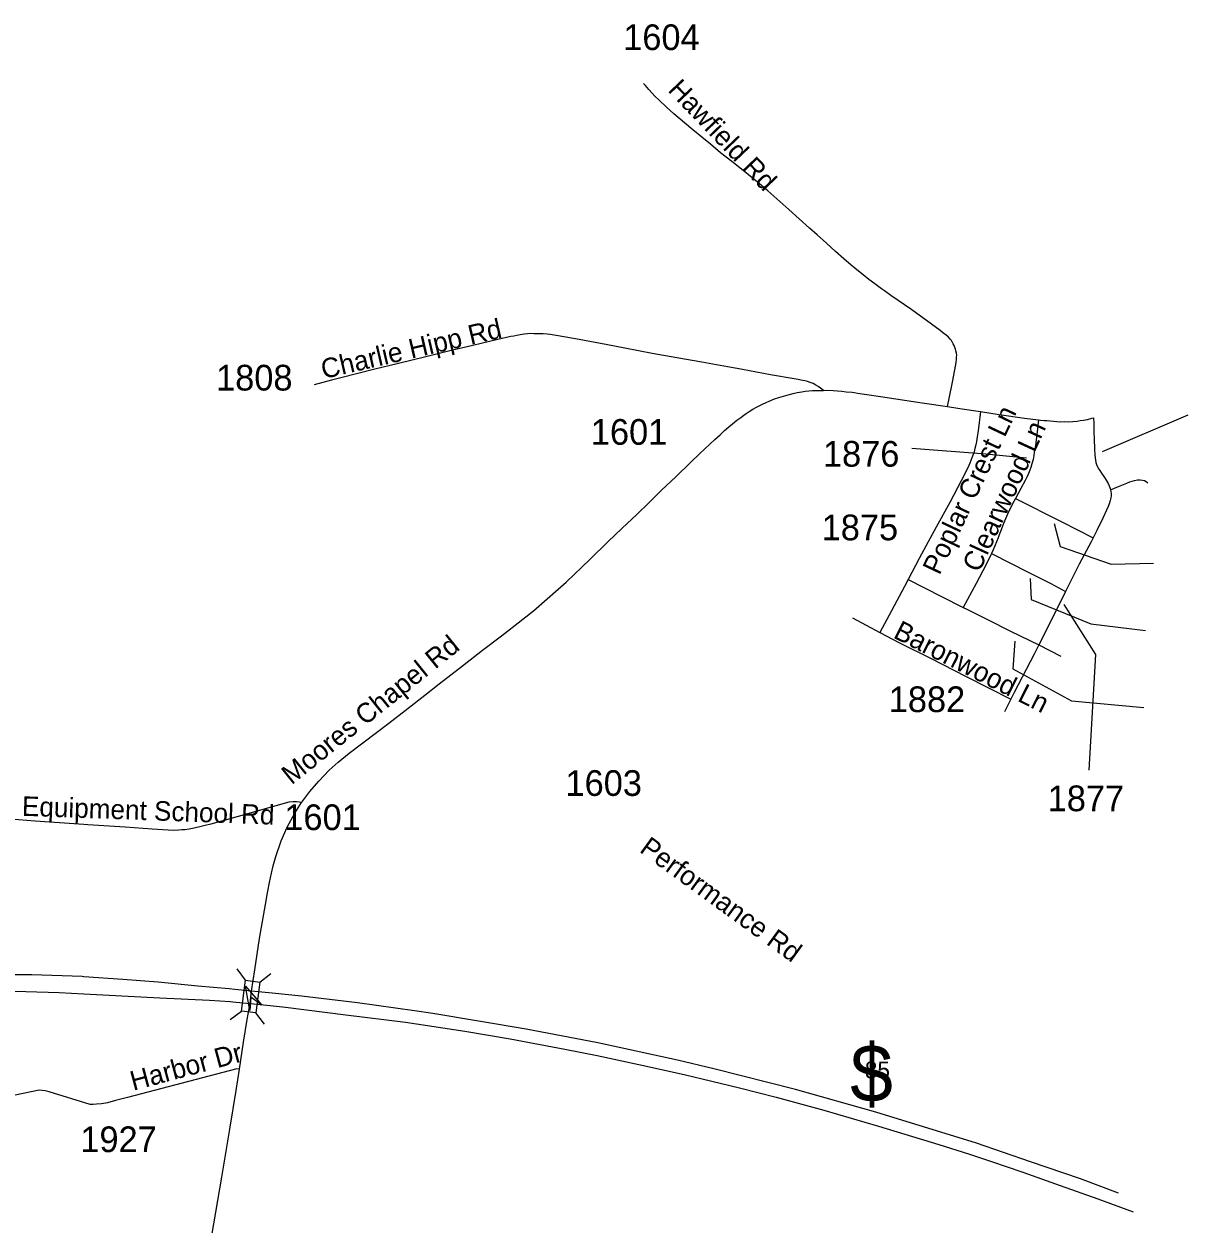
# Model space of a CAD drawing. Extents: x 1364363 to 1407445, y 538563 to 573342.
# Drawn here: x 1401783 to 1407445, y 553749 to 559586 of the extents above; entities that cross this region are included whole.
import ezdxf

# ---------------------------------------------------------------- set-up
doc = ezdxf.new("R2010")
doc.units = 0
for name, color, linetype in [('Default', 7, 'Continuous'), ('Exist Road Primary Interstate Divided Center Attributed', 7, 'Continuous'), ('Exist Road Primary Interstate Shield CELL', 7, 'Continuous'), ('Exist Road Secondary Structure Standard Bridge Attributed CELL', 7, 'Continuous'), ('Exist Road Secondary Structure Standard Bridge CELL', 7, 'Continuous'), ('Exist Road Secondary Type 51 Attributed', 7, 'Continuous'), ('Exist Road Secondary Type 51 Label', 7, 'Continuous'), ('Exist Road Secondary Type 51 Number Label', 7, 'Continuous')]:
    doc.layers.add(name, color=color, linetype=linetype)

msp = doc.modelspace()

# ---------------------------------------------------------------- linework, layer by layer
at = {"layer": 'Exist Road Primary Interstate Divided Center Attributed'}
for points in [[(1402889.9, 554881.6), (1402809.6, 554889.8), (1402781.4, 554892.7), (1402628.7, 554906.1), (1402436.1, 554924.4), (1402264.4, 554938.2), (1402075, 554951.4), (1402066.2, 554951.9), (1401820.9, 554959.8), (1401703.2, 554961.2), (1401454.2, 554964.3), (1401140.9, 554963), (1400812.9, 554956.8), (1400615.7, 554948.8), (1400380.2, 554939.8), (1400229.5, 554933.3), (1400151.5, 554930.7), (1400046.8, 554927.3), (1399813.2, 554921.2), (1399668.9, 554919.2), (1399415.1, 554904.8), (1399267.1, 554899.4), (1398949.5, 554886), (1398849.6, 554881.8)], [(1398871.8, 554808), (1399139.7, 554819.3), (1399383.9, 554824.3), (1399558.4, 554831.4), (1399816.6, 554844.8), (1399967.8, 554848.3), (1400081.5, 554856), (1400107.8, 554857.8), (1400231.2, 554866.9), (1400703.7, 554883.3), (1401109.6, 554891.3), (1401566.5, 554885.6), (1401573.3, 554885.6), (1401953.8, 554874.5), (1402075, 554867.8), (1402227.7, 554859.3), (1402444.7, 554849.5), (1402685, 554837.7), (1402785.5, 554830.5), (1402799.6, 554829.3), (1402883.2, 554821.9)], [(1407107.1, 553899.3), (1406922.5, 553967.7), (1406679.8, 554051.5), (1406415.7, 554141.3), (1405927.6, 554293.3), (1405535.4, 554403.2), (1405139.5, 554502.8), (1404962.1, 554544.8), (1404574.2, 554629.1), (1404225.4, 554696.7), (1403771.2, 554771.9), (1403682.1, 554785.3), (1403405, 554824), (1403132.7, 554856.6), (1402990.2, 554871.2), (1402889.9, 554881.6)], [(1402883.2, 554821.9), (1402981.1, 554811.5), (1403055.8, 554803.3), (1403349.3, 554766.2), (1403639.3, 554730.4), (1403927.4, 554686.4), (1404147.8, 554648.5), (1404413.6, 554599.2), (1404571.6, 554567.5), (1404774.7, 554524.1), (1404995.3, 554475), (1405263.1, 554411.3), (1405442.5, 554365.5), (1405674, 554302.7), (1405939.6, 554223.7), (1406233.8, 554135.9), (1406377.3, 554090.6), (1406489.5, 554052.4), (1406641.3, 554001.4), (1406824.2, 553936.6), (1407006.2, 553870.3), (1407178.2, 553807)]]:
    msp.add_lwpolyline(points, dxfattribs=at)
at = {"layer": 'Exist Road Secondary Structure Standard Bridge Attributed CELL'}
msp.add_lwpolyline([(1402882.6, 554786.3), (1402860.2, 554906.2), (1402939.5, 554813.5), (1402886.5, 554851.2)], close=True, dxfattribs=at)
at = {"layer": 'Exist Road Secondary Structure Standard Bridge CELL'}
for p, q in [((1402861.3, 554934.2), (1402819.4, 554989)), ((1402929.7, 554925.1), (1402984.5, 554967)), ((1402786.2, 554742.5), (1402841, 554784.5)), ((1402952.9, 554720.3), (1402911, 554775.1))]:
    msp.add_line(p, q, dxfattribs=at)
msp.add_lwpolyline([(1402841, 554784.5), (1402861, 554934.2), (1402931, 554924.9), (1402911, 554775.1)], close=True, dxfattribs=at)
at = {"layer": 'Exist Road Secondary Type 51 Attributed'}
for p, q in [((1405812.6, 556696.7), (1405946.8, 556626.2)), ((1406719.3, 556565), (1406826, 556511.2)), ((1406583.3, 556301.2), (1406553.3, 556240.4))]:
    msp.add_line(p, q, dxfattribs=at)
for points in [[(1406275.3, 557724.3), (1406297.2, 557827.6), (1406302.1, 557852.1), (1406314.8, 557921.1), (1406317.6, 557939.6), (1406319.3, 557955.1), (1406319.7, 557964.4), (1406320.2, 557974.6), (1406319.2, 557983.7), (1406316.5, 557995.6), (1406314.4, 558003.7), (1406311.7, 558011.2), (1406307.3, 558022.2), (1406303.5, 558030.3), (1406298.7, 558039.4), (1406294.1, 558046), (1406288.2, 558053), (1406280, 558061.7), (1406267.2, 558072.9), (1406259.8, 558079), (1406249.5, 558087), (1406240.5, 558094.4), (1406197.9, 558126), (1406101.7, 558196), (1406000.4, 558265.7), (1405969.2, 558287.8), (1405953.9, 558298.1), (1405921.4, 558321.7), (1405893.3, 558342.9), (1405864.7, 558365.8), (1405835, 558390.3), (1405807.6, 558412.5), (1405771.6, 558443.4), (1405731.1, 558479.4), (1405686.6, 558518.7), (1405641.5, 558559.7), (1405604.5, 558592.2), (1405502.9, 558683.9), (1405401, 558774.4), (1405350.5, 558815.9), (1405289.9, 558865.9), (1405225.7, 558917.3), (1405171.9, 558959.5), (1405121.9, 559001.1), (1405080.8, 559034.7), (1405036.9, 559070.6), (1404996, 559104.8), (1404943.8, 559148.9), (1404907.1, 559183.2), (1404872.4, 559215.5), (1404851.9, 559234.8), (1404838.2, 559249.1), (1404822.3, 559267.5), (1404814.2, 559276.4), (1404806.3, 559286.1), (1404798.9, 559294.1), (1404797.1, 559295.9)], [(1405671.8, 557803.6), (1405658.4, 557814), (1405647, 557822), (1405635, 557829.4), (1405621.9, 557836.3), (1405607.6, 557841.9), (1405593.9, 557846.5), (1405580.8, 557849.9), (1405562, 557853.9), (1405548.5, 557856.5), (1405529.7, 557859.9), (1405414.3, 557879.3), (1405278.7, 557904.6), (1405270.7, 557906.1), (1405186.9, 557921.4), (1405079.7, 557940.8), (1404958.3, 557962.5), (1404839.6, 557983), (1404706.3, 558009.1), (1404613.6, 558026.6), (1404483.4, 558051.4), (1404382.3, 558068.5), (1404342.1, 558074.5), (1404327.4, 558076.4), (1404307.9, 558078), (1404286.3, 558078.8), (1404263.2, 558079.2), (1404248.3, 558079.4), (1404232.9, 558078.3), (1404215.5, 558076.1), (1404197, 558073.7), (1404196.8, 558073.7), (1404180.2, 558071), (1404166.6, 558067.9), (1404152, 558065.2), (1404130.8, 558060.5), (1404088.7, 558051), (1403966.8, 558021.3), (1403848.8, 557993.9), (1403770.5, 557975), (1403725.1, 557964.1), (1403683.6, 557954.1), (1403597.7, 557932.8), (1403489.5, 557906.7), (1403324.5, 557865.2), (1403278.5, 557853.6), (1403195.1, 557830.5)], [(1404135.2, 556631.5), (1404172.8, 556660.8), (1404261, 556731.7), (1404327.6, 556789), (1404368.2, 556824.6), (1404419.9, 556870.4), (1404535.8, 556981.3), (1404623.7, 557066), (1404693.7, 557133.4), (1404763.5, 557199.5), (1404823.9, 557257.6), (1404884.9, 557318), (1404953.3, 557383), (1405024.6, 557451.9), (1405070.8, 557495.8), (1405119.6, 557542.2), (1405143.4, 557564), (1405169, 557588), (1405191.1, 557608), (1405212.1, 557626.3), (1405229.1, 557640.2), (1405250.9, 557658.2), (1405269.6, 557672.1), (1405284.8, 557683.4), (1405296.6, 557691.3), (1405310.6, 557701.2), (1405328.9, 557712), (1405346.5, 557722.3), (1405362.9, 557730.6), (1405376.2, 557737.1), (1405393.3, 557745.1), (1405408.1, 557751.4), (1405433.8, 557761.6), (1405455, 557768.8), (1405477.6, 557775.6), (1405500.7, 557782.3), (1405524.4, 557788.4), (1405544.9, 557792.4), (1405566.2, 557796.7), (1405583.8, 557798.9), (1405600.9, 557801.2), (1405618, 557802.3), (1405639, 557803.2), (1405671.8, 557803.6)], [(1405671.8, 557803.6), (1405680.2, 557803.7), (1405719.1, 557802.4), (1405761.9, 557799.1), (1405783.2, 557796.9), (1405811.6, 557794), (1405848.3, 557788.7), (1405883.7, 557783.5), (1405949.4, 557773), (1406151.6, 557743.1), (1406275.3, 557724.3)], [(1406275.3, 557724.3), (1406334.6, 557715.2), (1406435.5, 557700)], [(1406435.5, 557700), (1406432.5, 557673.9), (1406429.1, 557647.6), (1406425.7, 557619.2), (1406422.8, 557596.4), (1406420, 557576.7), (1406416.1, 557555.4), (1406412.8, 557538.6), (1406408.3, 557520.1), (1406404.4, 557505.1), (1406400, 557491.4), (1406393.9, 557474.7), (1406383.7, 557449.9), (1406373.6, 557426.9), (1406342.4, 557363.3), (1406286.1, 557257.6), (1406220.6, 557138), (1406181.2, 557066), (1406138.3, 556985.3), (1406084.5, 556884.1)], [(1406435.5, 557700), (1406526.1, 557686.7), (1406650.5, 557668.6), (1406717.6, 557660.2)], [(1406717.6, 557660.2), (1406727.2, 557659), (1406744.9, 557657.3), (1406758.6, 557656.2), (1406774.7, 557654.8), (1406791.6, 557653.3), (1406808, 557652.2), (1406824.7, 557651.1), (1406845.9, 557651.4), (1406863.2, 557650.9), (1406884.8, 557652.1), (1406905.6, 557653.9), (1406921, 557656.2), (1406937.7, 557659.3), (1406956.4, 557662.5), (1406977.6, 557667.9), (1406986.2, 557670.6)], [(1406986.2, 557670.6), (1406986.7, 557641.1), (1406986.7, 557621.2), (1406987.3, 557598.4), (1406988.4, 557568.7), (1406990.6, 557516), (1406991.7, 557490.4), (1406993, 557475.3), (1406994.7, 557463.3), (1406996.8, 557452.2), (1407000.4, 557443.4), (1407005.5, 557431.4), (1407011.2, 557420.6), (1407015.8, 557413.2), (1407024.9, 557400.1), (1407038.6, 557379.6), (1407047.2, 557366.5), (1407056.9, 557350.2), (1407062, 557339.7), (1407065.2, 557331.3), (1407068.2, 557321.4), (1407068.6, 557319.9)], [(1406717.6, 557660.2), (1406710.8, 557601.8), (1406707.8, 557575.9), (1406704.6, 557548.8), (1406702.8, 557535.1), (1406700.6, 557519.7), (1406697.7, 557502.6), (1406695.4, 557486.7), (1406691.4, 557467.3), (1406686.3, 557446.8), (1406680.6, 557428.6), (1406675.5, 557415.5), (1406669.2, 557399.5), (1406662.4, 557384.1), (1406653.2, 557365.3), (1406632.2, 557325.4), (1406605.7, 557277.1)], [(1407068.6, 557319.9), (1407070.3, 557311), (1407071, 557301.2), (1407071, 557291), (1407069.8, 557281.3), (1407067.1, 557267.9), (1407063.7, 557255.9), (1407060.1, 557247.1), (1407056.7, 557238), (1407049.3, 557221.4), (1407031.2, 557182.4), (1407001, 557121.4), (1406983.6, 557085.8)], [(1407068.6, 557319.9), (1407107, 557335.7), (1407147.5, 557352.2), (1407162.9, 557357.9), (1407174.3, 557361.9), (1407185.7, 557365.3), (1407199.9, 557367.6), (1407212.5, 557368.2), (1407223.9, 557367), (1407232.9, 557364.5), (1407242, 557360.5), (1407250, 557353.6)], [(1406605.7, 557277.1), (1406591.9, 557251.1), (1406567.7, 557201.8), (1406547.8, 557155.6), (1406535.7, 557125.7), (1406526.4, 557101.1), (1406521.2, 557086.4), (1406513.9, 557066), (1406498, 557027.3), (1406489.4, 557010.2)], [(1406605.7, 557277.1), (1406831.8, 557164.2), (1406983.6, 557085.8)], [(1406983.6, 557085.8), (1406974, 557066), (1406916.5, 556957.6), (1406850.1, 556825.5)], [(1406489.4, 557010.2), (1406462.9, 556956.8), (1406414.7, 556863.6), (1406352.4, 556748)], [(1406489.4, 557010.2), (1406671.1, 556917.9), (1406777.9, 556864), (1406850.1, 556825.5)], [(1406084.5, 556884.1), (1406066.1, 556849.5), (1406003.7, 556730.3), (1405946.9, 556626.3), (1405946.8, 556626.2)], [(1406084.5, 556884.1), (1406247, 556801.6), (1406352.4, 556748)], [(1406850.1, 556825.5), (1406787.8, 556700.8), (1406719.3, 556565)], [(1406352.4, 556748), (1406368.8, 556739.7), (1406469.3, 556689.3), (1406581.6, 556633), (1406719.1, 556565.1), (1406719.3, 556565)], [(1403132.9, 555798.2), (1403134.1, 555800.2), (1403173.8, 555852.3), (1403217.4, 555902.2), (1403268, 555955.7), (1403312.2, 555994.8), (1403365.6, 556039), (1403431.2, 556089.4), (1403557.6, 556185.1), (1403651.8, 556257.9), (1403732.6, 556320.1), (1403802.6, 556375.4), (1403916.2, 556463.5), (1404013.2, 556539.4), (1404106.6, 556609.1), (1404135.2, 556631.5)], [(1405946.8, 556626.2), (1406042.3, 556575.8), (1406193.3, 556500.4), (1406366.4, 556412.4), (1406583.3, 556301.2)], [(1406719.3, 556565), (1406697, 556520.9), (1406599.5, 556334), (1406583.3, 556301.2)], [(1403132.9, 555798.2), (1403121.9, 555799.7), (1403108.4, 555801.8), (1403093.4, 555802.5), (1403071.5, 555799.7), (1403008.6, 555781.8), (1402824.8, 555730.6), (1402732.2, 555704.2), (1402692.3, 555692.8), (1402665, 555686.5), (1402645.6, 555681.9), (1402610.4, 555674.5), (1402586.6, 555669.5), (1402566, 555666.5), (1402551.5, 555665.2), (1402536.5, 555664.4), (1402508.8, 555663.4), (1402485.2, 555664.3), (1402407.5, 555668.5), (1402275.5, 555678.5), (1402093.3, 555689.8), (1402075, 555691.1), (1401837.7, 555708.6), (1401715.5, 555717.5)], [(1402889.9, 554881.6), (1402905.7, 554985.2), (1402929.3, 555137.3), (1402958.1, 555302), (1402967.9, 555359.4), (1402969.4, 555366.8), (1402978, 555409.9), (1402986.7, 555455.8), (1402994.9, 555491.5), (1403007.5, 555536.4), (1403033.9, 555612.2), (1403064.2, 555679.5), (1403101.1, 555746.8), (1403132.9, 555798.2)], [(1402883.2, 554821.9), (1402886.5, 554851.2), (1402889.9, 554881.6)], [(1402831.7, 554501.6), (1402850.5, 554632.6), (1402869.6, 554743), (1402883.2, 554821.9)], [(1402831.7, 554501.6), (1402818.9, 554503.6), (1402286.6, 554364.3), (1402228.5, 554348.5), (1402189.6, 554338.7), (1402159.7, 554333.1), (1402135.7, 554330.7), (1402119.7, 554329.5), (1402105.5, 554330.1), (1401905.4, 554391.2), (1401885.5, 554395.9), (1401857.3, 554400.1), (1401660.3, 554358.8)], [(1402683, 553605.6), (1402707.3, 553749.2), (1402745.8, 553976.3), (1402784.7, 554210.5), (1402815.2, 554397.2), (1402831.7, 554501.6)]]:
    msp.add_lwpolyline(points, dxfattribs=at)
at = {"layer": 'Exist Road Secondary Type 51 Number Label'}
for points in [[(1407028.7, 557506.9), (1407445.3, 557684.9)], [(1406659, 557474.2), (1406462.5, 557492.9), (1406102.1, 557521)], [(1406794.7, 557155.7), (1406822.8, 557043.3), (1407070.9, 556958.9), (1407276.8, 556963.6)], [(1406677.7, 556888.7), (1406682.4, 556785.6), (1406972.6, 556668.6), (1407239.3, 556635.8)], [(1406841.5, 556762.2), (1406996, 556518.7), (1406963.2, 555956.6)], [(1406602.9, 556584.2), (1406593.5, 556448.4), (1406879, 556293.9), (1407230, 556261.1)]]:
    msp.add_lwpolyline(points, dxfattribs=at)

# ---------------------------------------------------------------- texts
at = {"layer": 'Default'}
msp.add_text('$', height=278.9, dxfattribs=at).set_placement((1405802, 554342.1))
at = {"layer": 'Exist Road Primary Interstate Shield CELL'}
msp.add_text('85', height=82.02, dxfattribs=at).set_placement((1405873.5, 554456.9))
at = {"layer": 'Exist Road Secondary Type 51 Label'}
for s, rotation, p in [('Hawfield Rd', 313.66829, (1404911.1, 559261.2)), ('Charlie Hipp Rd', 13.07781, (1403240.5, 557858.3)), ('Poplar Crest Ln', 64.67915, (1406236.3, 556900.8)), ('Clearwood Ln', 65.3375, (1406430, 556913.4)), ('Baronwood Ln', 333.04187, (1406006.7, 556602.9)), ('Moores Chapel Rd', 38.84477, (1403084.9, 555881.8)), ('Heavy Equipment School Rd', 357.9817, (1401376.9, 555748.3)), ('Performance Rd', 323.96212, (1404772.3, 555561.4)), ('Harbor Dr', 15.06316, (1402314.6, 554396.3))]:
    msp.add_text(s, height=95, rotation=rotation, dxfattribs=at).set_placement(p)
at = {"layer": 'Exist Road Secondary Type 51 Number Label'}
for s, p in [('1604', (1404698, 559458.7)), ('1808', (1402717.6, 557802.7)), ('1601', (1404540.6, 557538.9)), ('1876', (1405669.5, 557432.3)), ('1875', (1405663.3, 557074.3)), ('1882', (1405989.7, 556238.5)), ('1603', (1404417.3, 555830.9)), ('1877', (1406762.8, 555756.5)), ('1601', (1403049.6, 555664.6)), ('1927', (1402057.4, 554098.1))]:
    msp.add_text(s, height=125, dxfattribs=at).set_placement(p)

doc.saveas('drawing.dxf')
